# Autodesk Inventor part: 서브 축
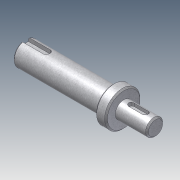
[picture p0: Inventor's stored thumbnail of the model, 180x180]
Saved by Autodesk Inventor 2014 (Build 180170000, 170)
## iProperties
Company: 한국ATC센터
Created: 2014-10
Part Number: 서브 축
Document SubType Name: Modeling
Designer: KYOUNG IL JANG
Density: 1 g/cm^3
Mass: 19.9624 g
Surface Area: 57.7178 cm^2
Volume: 19.9624 cm^3
Material: 일반
Appearance: 금속-강(스테인리스, 브러시됨)
Author: KYOUNG IL JANG
Revision Number: 1
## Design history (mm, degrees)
sketch "스케치1"
  geometry: L1 (-16.331, 0)-(-108.831, 0); L2 (-16.331, 0)-(-16.331, -6); L3 (-16.331, -6)-(-38.831, -6); L4 (-38.831, -12.5)-(-46.5, -12.5); L5 (-46.5, -8.5)-(-108.831, -8.5); L6 (-108.831, -8.5)-(-108.831, 0); L7 (-46.5, -8.5)-(-46.5, -12.5); L8 (-38.831, -6)-(-38.831, -12.5); L9 (-46.5, 12.249)-(-46.5, -12.249) reference; L10 (-38.831, -17)-(-38.831, 17) reference; 2 further points
  constraints: 17 end point, 4 perpendicular, 2 collinear, 2 parallel, 1 horizontal, 1 midpoint, 1 point on line
  dimensions: "d1" = 12 diameter of L3 L1; "d2" = 25 diameter of L4 L1; "d3" = 17 diameter of L5 L1; "d4" = 62.33128 distance of L5.start L5.end (derived); "d18" = 22.5 distance of L2.end L3.end; "d20" = 70 distance between parallel lines of L6 L8
revolve "회전1" sketch "스케치1" stored, may be unused: angle "d5" = 90 deg
chamfer "모따기1" distance "d6" = 1; stored, may be unused: second distance "d7" = 2, angle "d8" = 45 deg
node "작업 평면1"
sketch "스케치2"
  geometry: L1 (11.25, 5)-(11.25, -5) reference; L2 (-5.75, -2)-(4.25, -2); L3 (4.25, 2)-(-5.75, 2); A1 r 2 centre (4.25, 0) between (4.25, -2) and (4.25, 2); A2 r 2 centre (-5.75, 0) between (-5.75, 2) and (-5.75, -2); 2 further points
  constraints: 4 end point, 4 point on circle, 4 tangent, 2 centre point, 1 horizontal alignment, 1 midpoint, 1 parallel, 1 perpendicular
  dimensions: "d9" = 4 distance between parallel lines of L2 L3; "d10" = 14 dimension on A1 A2; "d11" = 5 distance edge to line of A1 L1
extrude "돌출1" cut sketch "스케치2" distance "d12" = 2.5; taper "d13" = 0 deg
node "작업 평면2"
sketch "스케치3"
  geometry: L1 (-31.166, -7.5)-(-31.166, 7.5) reference; L2 (-31.166, 2.5)-(-15.666, 2.5); L3 (-15.666, -2.5)-(-31.166, -2.5); A1 r 2.5 centre (-15.666, 0) between (-15.666, -2.5) and (-15.666, 2.5); 2 further points
  constraints: 4 end point, 2 perpendicular, 2 point on circle, 2 point on line, 2 tangent, 1 centre point, 1 horizontal alignment, 1 midpoint
  dimensions: "d14" = 5 distance between parallel lines of L3 L2; "d15" = 18 dimension on A1 L1
extrude "돌출2" cut sketch "스케치3" distance "d16" = 3; taper "d17" = 0 deg
node "솔리드1"
node "참조4"
node "참조5"
